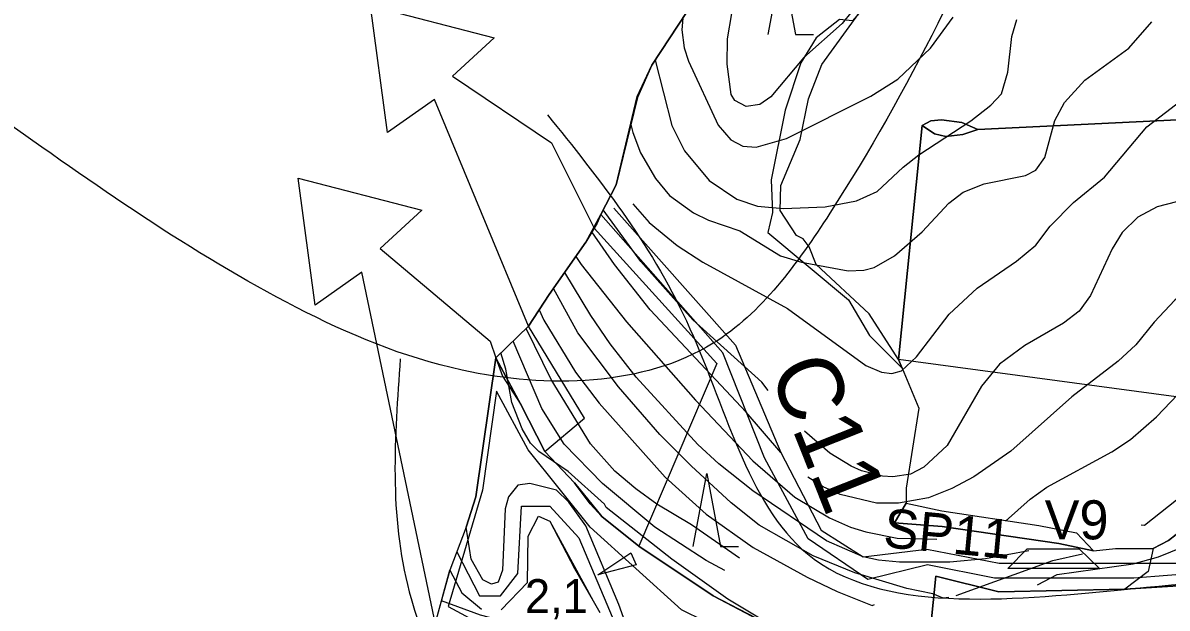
# Model space of a CAD drawing. Extents: x -684583 to -680383, y -1157874 to -1154904.
# Drawn here: x -683807 to -683367.4, y -1156883.6 to -1156658.6 of the extents above; entities that cross this region are included whole.
import ezdxf

# ---------------------------------------------------------------- set-up
doc = ezdxf.new("R2010")
doc.units = 0
for name, color, linetype in [('01_OBVOD PÚ', 7, 'Continuous'), ('01_PRVKY PRŮZKUMU', 7, 'Continuous'), ('01_SPRÁV_HRANICE', 7, 'Continuous'), ('01_VRSTEVNICE', 7, 'Continuous'), ('02_KULTURY STAV', 7, 'Continuous'), ('03_PC_OBJEKTY_NÁVRH', 7, 'Continuous'), ('03_PC_POPIS_STAV', 7, 'Continuous'), ('03_PC_STAV', 7, 'Continuous'), ('05_VHO_V_TOK', 7, 'Continuous'), ('06_BIOGEOGRAFIE', 7, 'Continuous'), ('06_ÚSES_BK', 7, 'Continuous')]:
    doc.layers.add(name, color=color, linetype=linetype)

msp = doc.modelspace()

# ---------------------------------------------------------------- linework, layer by layer
at = {"layer": '01_OBVOD PÚ'}
for points in [[(-683524.73, -1156612.92), (-683565.38, -1156674.86), (-683570.93, -1156687.37), (-683579.12, -1156720.91), (-683585.06, -1156732.32), (-683586.41, -1156735.62), (-683590.79, -1156742.99), (-683604.88, -1156763.1), (-683612.82, -1156775.26), (-683625.32, -1156787.43), (-683633.07, -1156840.81), (-683636.72, -1156852.51)], [(-683636.72, -1156852.51), (-683643.02, -1156869.04), (-683649.36, -1156892.03), (-683671.07, -1156923.59), (-683731.15, -1157006.91), (-683731.15, -1157006.91), (-683753.8, -1157039.59), (-683758.87, -1157046.08), (-683790.05, -1157085.64), (-683814.83, -1157112.74)], [(-683355.2, -1156936.88), (-683380.8, -1156922.96), (-683394.92, -1156921.16), (-683404.54, -1156921.9), (-683418.18, -1156922.4), (-683413.73, -1156906.92), (-683459.39, -1156901.7), (-683456.29, -1156871.3), (-683432.04, -1156877.37), (-683383.68, -1156876.28), (-683357.1, -1156874.68)], [(-683357.1, -1156874.68), (-683383.68, -1156876.28), (-683432.04, -1156877.37), (-683456.29, -1156871.3), (-683459.39, -1156901.7), (-683413.22, -1156907.01), (-683418.18, -1156922.4), (-683394.92, -1156921.16), (-683380.8, -1156922.96), (-683355.2, -1156936.88)]]:
    msp.add_lwpolyline(points, dxfattribs=at)
at = {"layer": '01_PRVKY PRŮZKUMU'}
msp.add_lwpolyline([(-683356.94, -1156938.03), (-683380.59, -1156925.22), (-683395.1, -1156922.91), (-683418.63, -1156924.37), (-683420.21, -1156922.66), (-683416.44, -1156909.37), (-683459.35, -1156905.59), (-683501.04, -1156910.34), (-683553.95, -1156884.24), (-683589.06, -1156852.53), (-683612.95, -1156822.77), (-683625.02, -1156800.2), (-683630.51, -1156838.26), (-683643.68, -1156883.02), (-683591.38, -1156911.2), (-683539.08, -1156946.2), (-683515.55, -1156959.38), (-683497.63, -1156981.82), (-683487.39, -1157002.43), (-683470.08, -1157010.97), (-683441.67, -1157010.97), (-683424.51, -1157001.8), (-683389.86, -1156998.77), (-683362.19, -1157001.09)], dxfattribs=at)
at = {"layer": '01_SPRÁV_HRANICE'}
for points in [[(-683524.73, -1156612.92), (-683565.38, -1156674.86), (-683570.93, -1156687.37), (-683579.12, -1156720.91), (-683585.06, -1156732.32), (-683586.41, -1156735.62), (-683590.79, -1156742.99), (-683604.88, -1156763.1), (-683612.82, -1156775.26), (-683625.32, -1156787.43), (-683633.07, -1156840.81), (-683636.72, -1156852.51)], [(-683636.72, -1156852.51), (-683643.02, -1156869.04), (-683649.36, -1156892.03), (-683671.07, -1156923.59), (-683731.15, -1157006.91), (-683731.15, -1157006.91), (-683753.8, -1157039.59), (-683758.87, -1157046.08), (-683790.05, -1157085.64), (-683814.83, -1157112.74)]]:
    msp.add_lwpolyline(points, dxfattribs=at)
at = {"layer": '01_VRSTEVNICE'}
for points in [[(-683572.71, -1156728.24), (-683566.43, -1156735.37), (-683555.73, -1156744.22), (-683545.75, -1156750.63), (-683513.23, -1156768.46), (-683483.13, -1156790.29), (-683477.14, -1156792.86), (-683473.14, -1156793.43), (-683469.43, -1156792.43), (-683463.73, -1156787.01), (-683451.18, -1156770.6), (-683440.48, -1156760.62), (-683425.36, -1156750.21), (-683417.94, -1156744.07), (-683412.38, -1156736.8), (-683403.39, -1156727.67), (-683391.55, -1156717.97), (-683375.29, -1156698.57), (-683353.75, -1156682.02), (-683350.9, -1156679.03), (-683344.48, -1156669.18), (-683338.35, -1156661.34), (-683330.07, -1156653.92)], [(-683488.55, -1156654.21), (-683492.26, -1156658.91), (-683506.95, -1156671.89), (-683519.65, -1156687.01), (-683523.92, -1156690.01), (-683529.2, -1156690.72), (-683533.48, -1156688.44), (-683534.91, -1156686.16), (-683536.48, -1156674.46), (-683536.33, -1156664.76), (-683534.62, -1156655.06)], [(-683573.46, -1156697.72), (-683572.71, -1156700.71), (-683569.71, -1156708.55), (-683564.01, -1156718.4), (-683558.59, -1156724.96), (-683549.46, -1156731.66), (-683543.61, -1156734.52), (-683531.63, -1156738.51), (-683515.94, -1156748.21), (-683507.95, -1156750.63), (-683489.98, -1156753.91), (-683483.98, -1156753.63), (-683479.99, -1156752.63), (-683472.15, -1156748.21), (-683461.59, -1156738.94), (-683451.32, -1156727.95), (-683445.76, -1156723.67), (-683437.77, -1156720.54), (-683421.79, -1156717.26), (-683417.94, -1156715.26), (-683414.37, -1156710.41), (-683410.52, -1156696.14), (-683406.82, -1156689.3), (-683399.11, -1156680.6), (-683382.14, -1156668.33), (-683373.29, -1156658.2)], [(-683564.15, -1156672.99), (-683557.73, -1156698.14), (-683552.88, -1156707.84), (-683543.33, -1156719.25), (-683532.77, -1156726.38), (-683524.78, -1156729.09), (-683514.8, -1156729.95), (-683498.82, -1156729.38), (-683486.84, -1156727.1), (-683478.85, -1156723.39), (-683468.86, -1156714.12), (-683462.87, -1156709.41), (-683442.9, -1156696.29), (-683435.2, -1156690.3), (-683431.06, -1156685.87), (-683428.64, -1156677.6), (-683427.07, -1156663.91), (-683425.21, -1156657.35)], [(-683553.5, -1156656.76), (-683553.88, -1156661.34), (-683553.03, -1156668.19), (-683551.31, -1156673.32), (-683539.9, -1156698), (-683535.05, -1156703.56), (-683530.49, -1156705.99), (-683525.35, -1156706.41), (-683513.66, -1156703.13), (-683481.28, -1156686.87), (-683470.86, -1156680.31), (-683458.31, -1156668.33), (-683449.61, -1156656.49)], [(-683251.9, -1156698), (-683255.04, -1156700.57), (-683268.88, -1156708.98), (-683291.13, -1156719.82), (-683314.24, -1156736.8), (-683322.8, -1156741.51), (-683338.77, -1156748.64), (-683355.04, -1156757.48), (-683364.45, -1156765.18), (-683372.44, -1156773.74), (-683379.43, -1156782.44), (-683386.27, -1156788.72), (-683404.1, -1156802.41), (-683427.5, -1156823.24), (-683441.76, -1156833.08), (-683450.18, -1156837.65), (-683459.17, -1156841.21), (-683470.58, -1156843.21), (-683479.13, -1156843.21), (-683493.11, -1156839.93), (-683499.58, -1156836.93), (-683505.52, -1156833.22)], [(-683355.89, -1156725.39), (-683371.3, -1156729.38), (-683378.71, -1156733.38), (-683384.7, -1156739.22), (-683388.56, -1156745.5), (-683396.83, -1156763.47), (-683401.25, -1156769.46), (-683407.24, -1156774.03), (-683422.08, -1156782.59), (-683431.78, -1156789.86), (-683438.77, -1156798.28), (-683451.89, -1156821.1), (-683460.88, -1156829.37), (-683466.01, -1156832.08), (-683472.86, -1156833.08), (-683476.85, -1156832.94), (-683484.84, -1156830.8), (-683488.83, -1156829.09), (-683496.96, -1156824.1), (-683506.81, -1156815.54)], [(-683520.7, -1156800), (-683523.17, -1156796.7), (-683549.6, -1156772.74), (-683569.57, -1156750.35), (-683584.1, -1156730.47)], [(-683515.79, -1156823.81), (-683529.2, -1156808.26), (-683566, -1156768.89), (-683579.7, -1156751.49), (-683588.42, -1156739)], [(-683594.62, -1156748.46), (-683592.54, -1156751.49), (-683575.13, -1156773.6), (-683548.6, -1156803.7), (-683526.63, -1156826.95), (-683510.52, -1156840.93), (-683497.11, -1156848.92), (-683489.12, -1156852.48), (-683483.13, -1156854.34), (-683471.15, -1156856.76), (-683455.88, -1156857.05)], [(-683420.51, -1156861.61), (-683437.2, -1156864.61), (-683450.89, -1156865.89), (-683470.29, -1156865.89), (-683478.28, -1156865.18), (-683484.27, -1156863.89), (-683498.25, -1156857.76), (-683526.63, -1156838.5), (-683539.62, -1156828.09), (-683547.75, -1156820.67), (-683571.43, -1156794.85), (-683581.41, -1156782.02), (-683588.83, -1156771.18), (-683598.89, -1156754.55)], [(-683451.32, -1156879.58), (-683453.46, -1156879.73), (-683457.45, -1156878.16), (-683467.44, -1156876.02), (-683487.41, -1156870.03), (-683503.38, -1156863.47), (-683524.21, -1156851.77), (-683534.91, -1156843.07), (-683550.31, -1156828.95), (-683562.3, -1156816.82), (-683578.27, -1156798.56), (-683593.82, -1156777.74), (-683603.22, -1156760.73)], [(-683429.5, -1156850.2), (-683420.08, -1156841.78), (-683413.66, -1156837.08), (-683388.7, -1156823.53), (-683381.57, -1156818.82), (-683371.58, -1156810.12), (-683349.61, -1156787.15), (-683341.06, -1156781.3), (-683335.92, -1156779.31), (-683325.65, -1156777.59), (-683305.11, -1156777.17), (-683297.41, -1156776.31), (-683284.57, -1156772.6), (-683272.16, -1156766.04)], [(-683608.73, -1156768.99), (-683606.94, -1156772.89), (-683594.68, -1156792.86), (-683585.69, -1156804.84), (-683560.3, -1156833.22), (-683544.47, -1156847.49), (-683526.49, -1156860.33), (-683505.67, -1156871.74), (-683494.25, -1156877.16), (-683480.7, -1156882.58), (-683479.85, -1156882.15)], [(-683531.77, -1156864.46), (-683550.17, -1156851.63), (-683563.44, -1156843.64), (-683571.57, -1156837.79), (-683579.56, -1156830.94), (-683588.97, -1156820.39), (-683604.09, -1156795.71), (-683613.74, -1156776.16)], [(-683537.33, -1156869.17), (-683544.47, -1156865.32), (-683564.29, -1156852.48), (-683584.41, -1156835.65), (-683599.1, -1156820.53), (-683607.66, -1156806.84), (-683618.68, -1156780.96)], [(-683355.46, -1156920.38), (-683357.32, -1156920.38), (-683359.6, -1156918.67), (-683379, -1156909.97), (-683394.41, -1156905.12), (-683416.09, -1156903.12), (-683451.6, -1156904.12), (-683467.44, -1156903.26), (-683488.83, -1156898.7), (-683514.51, -1156891.42), (-683524.64, -1156887.14), (-683536.19, -1156880.15), (-683557.73, -1156864.75), (-683582.98, -1156844.92), (-683583.55, -1156843.64), (-683597.53, -1156831.09), (-683608.8, -1156823.38), (-683612.08, -1156820.24), (-683615.22, -1156814.68), (-683619.21, -1156804.55), (-683621.49, -1156791.72), (-683623.36, -1156785.52)], [(-683377.43, -1156851.63), (-683376.15, -1156851.77), (-683360.74, -1156839.5), (-683354.04, -1156831.51), (-683343.2, -1156815.97), (-683336.49, -1156810.12), (-683328.5, -1156806.69), (-683318.95, -1156805.7)], [(-683417.2, -1156874.64), (-683409.69, -1156870.63), (-683380.43, -1156866.6), (-683370.73, -1156863.89), (-683361.31, -1156860.04), (-683353.04, -1156854.91), (-683343.05, -1156844.35), (-683334.49, -1156831.66), (-683329.5, -1156826.95), (-683322.66, -1156824.67), (-683321.23, -1156825.24), (-683321.23, -1156827.8), (-683323.8, -1156833.94), (-683324.79, -1156843.07), (-683326.65, -1156852.2), (-683334.21, -1156875.02), (-683341.63, -1156888.71), (-683343.48, -1156893.28), (-683343.91, -1156904.12), (-683340.48, -1156911.54), (-683337.2, -1156916.1), (-683322.65, -1156927.66)], [(-683448.47, -1156878.73), (-683411.38, -1156865.32), (-683399.97, -1156862.75)], [(-683361.6, -1157020.95), (-683377.57, -1157017.24), (-683390.7, -1157015.95), (-683403.25, -1157017.38), (-683419.51, -1157020.8), (-683438.34, -1157026.79), (-683453.74, -1157029.36), (-683464.3, -1157028.65), (-683471.43, -1157026.65), (-683476.71, -1157024.37), (-683484.27, -1157019.8), (-683492.26, -1157012.96), (-683503.81, -1156998.55), (-683513.08, -1156984.28), (-683523.5, -1156971.16), (-683530.2, -1156964.89), (-683542.04, -1156955.33), (-683549.74, -1156947.77), (-683573.14, -1156918.67), (-683594.96, -1156898.13), (-683604.95, -1156893.14), (-683631.19, -1156886.29), (-683646.27, -1156880.82)]]:
    msp.add_lwpolyline(points, dxfattribs=at)
at = {"layer": '02_KULTURY STAV'}
for points in [[(-683432.04, -1156877.37), (-683456.29, -1156871.3), (-683458.99, -1156897.79), (-683470.08, -1156900.87), (-683483.78, -1156902.23), (-683501.85, -1156899.69), (-683541.87, -1156878.91), (-683570.35, -1156859.85), (-683584.63, -1156848.32), (-683595.13, -1156835.42), (-683606.54, -1156823.38), (-683615.78, -1156805.32), (-683625.32, -1156787.43), (-683612.82, -1156775.26), (-683604.88, -1156763.1), (-683590.79, -1156742.99), (-683585.06, -1156732.32), (-683579.12, -1156720.91), (-683571, -1156686.89), (-683565.38, -1156674.86), (-683524.73, -1156612.92)], [(-683520.74, -1156663.07), (-683515.49, -1156635.07), (-683510.24, -1156663.07), (-683503.24, -1156663.07)], [(-683250.43, -1156639.58), (-683251.92, -1156662.61), (-683255.02, -1156690.63), (-683440.19, -1156699.57), (-683446.37, -1156696.93), (-683454.14, -1156695.86), (-683458.28, -1156696.29), (-683461.57, -1156698.06), (-683470.65, -1156788), (-683481.96, -1156770.49), (-683502.22, -1156751.48), (-683504.93, -1156744.71), (-683507.26, -1156741.71), (-683509.77, -1156740.38), (-683516.1, -1156730.82), (-683515.85, -1156721.2), (-683508.45, -1156703.51), (-683505.19, -1156687.78), (-683500.09, -1156674.67), (-683485.88, -1156655.07)], [(-683493.37, -1156657.35), (-683502.3, -1156664.33), (-683508.16, -1156673.98), (-683514.12, -1156692.19), (-683519.56, -1156719.01), (-683519.03, -1156731.5), (-683520.89, -1156739.21), (-683489.86, -1156765.12), (-683481.81, -1156778.8), (-683469.26, -1156791.35), (-683462.87, -1156806.79), (-683467.74, -1156837.5), (-683467.68, -1156843.29), (-683472.14, -1156850.86), (-683453.92, -1156852.18), (-683409.09, -1156858.82), (-683395.73, -1156861.57), (-683387.31, -1156860.69), (-683372.79, -1156860.68), (-683374.76, -1156869.57), (-683383.68, -1156876.28), (-683432.04, -1156877.37)], [(-683575.07, -1156890.75), (-683578.07, -1156882.16), (-683590.81, -1156851.97), (-683597.23, -1156842.93), (-683602, -1156838.28), (-683612.25, -1156835.71), (-683616.87, -1156836.4), (-683620.5, -1156840.84), (-683621.81, -1156845.41), (-683622.8, -1156868.99), (-683624.44, -1156873.64), (-683627.05, -1156874.36), (-683630.39, -1156872.73), (-683634.76, -1156864.74), (-683636.72, -1156852.51), (-683633.07, -1156840.81), (-683625.32, -1156787.43), (-683615.78, -1156805.32), (-683606.54, -1156823.38), (-683595.13, -1156835.42), (-683584.63, -1156848.32), (-683570.35, -1156859.85), (-683541.87, -1156878.91), (-683515.11, -1156893)], [(-683549.57, -1156859.91), (-683544.32, -1156831.91), (-683539.07, -1156859.91), (-683532.07, -1156859.91)], [(-683575.07, -1156890.75), (-683578.07, -1156882.16), (-683590.81, -1156851.97), (-683597.23, -1156842.93), (-683602, -1156838.28), (-683612.25, -1156835.71), (-683616.87, -1156836.4), (-683620.5, -1156840.84), (-683621.81, -1156845.41), (-683622.8, -1156868.99), (-683624.44, -1156873.64), (-683627.05, -1156874.36), (-683630.39, -1156872.73), (-683634.76, -1156864.74), (-683636.72, -1156852.51), (-683643.02, -1156869.04), (-683638.42, -1156877.73), (-683630.81, -1156883.98)], [(-683623.28, -1156884.31), (-683613.15, -1156873.71), (-683612.91, -1156855.89), (-683609, -1156848.24), (-683604.61, -1156850.24), (-683595.11, -1156868.31), (-683587.96, -1156880.75), (-683585.36, -1156885.34)], [(-683623.28, -1156884.31), (-683613.15, -1156873.71), (-683612.91, -1156855.89), (-683609, -1156848.24), (-683604.61, -1156850.24), (-683587.96, -1156880.75), (-683585.36, -1156885.34)], [(-683648.19, -1156887.79), (-683643.02, -1156869.04), (-683638.42, -1156877.73), (-683630.81, -1156883.98)], [(-683357.1, -1156874.68), (-683383.68, -1156876.28), (-683432.04, -1156877.37), (-683456.29, -1156871.3), (-683459.39, -1156901.7), (-683413.22, -1156907.01), (-683380.86, -1156914.04), (-683355.11, -1156929.55)]]:
    msp.add_lwpolyline(points, dxfattribs=at)
for points in [[(-683485.88, -1156655.07), (-683488.33, -1156657.8), (-683493.37, -1156657.35), (-683502.3, -1156664.33), (-683508.16, -1156673.98), (-683514.12, -1156692.19), (-683519.56, -1156719.01), (-683519.03, -1156731.5), (-683520.89, -1156739.21), (-683489.86, -1156765.12), (-683481.81, -1156778.8), (-683469.26, -1156791.35), (-683470.65, -1156788), (-683481.96, -1156770.49), (-683502.22, -1156751.48), (-683504.93, -1156744.71), (-683507.26, -1156741.71), (-683509.77, -1156740.38), (-683516.1, -1156730.82), (-683515.85, -1156721.2), (-683508.45, -1156703.51), (-683505.19, -1156687.78), (-683500.09, -1156674.67)], [(-683461.57, -1156698.06), (-683456.76, -1156701.28), (-683452.45, -1156702.26), (-683445.89, -1156701.53), (-683440.19, -1156699.57), (-683255.02, -1156690.63), (-683256.28, -1156728.52), (-683263.19, -1156747.9), (-683277, -1156775.83), (-683293.02, -1156802.11), (-683296.59, -1156809.49), (-683303.1, -1156808.51), (-683311.62, -1156809.46), (-683470.65, -1156788)], [(-683461.57, -1156698.06), (-683458.28, -1156696.29), (-683454.14, -1156695.86), (-683446.37, -1156696.93), (-683440.19, -1156699.57), (-683445.89, -1156701.53), (-683452.45, -1156702.26), (-683456.76, -1156701.28)], [(-683470.65, -1156788), (-683469.26, -1156791.35), (-683462.87, -1156806.79), (-683467.74, -1156837.5), (-683467.68, -1156843.29), (-683453.95, -1156846.2), (-683416.75, -1156851.8), (-683402.2, -1156854.64), (-683395.73, -1156861.57), (-683387.31, -1156860.69), (-683372.79, -1156860.68), (-683366.97, -1156857.64), (-683358.08, -1156850.72), (-683354.26, -1156850.68), (-683348.7, -1156844.45), (-683343.91, -1156825.46), (-683324.44, -1156813.27), (-683311.62, -1156809.46)], [(-683303.58, -1156846.39), (-683306.11, -1156845.61), (-683317.39, -1156851.59), (-683327.99, -1156859.69), (-683336.87, -1156864.5), (-683341.9, -1156865.49), (-683346.55, -1156863.74), (-683352.01, -1156858.95), (-683337.5, -1156844.95), (-683329.43, -1156828.36), (-683343.91, -1156825.46), (-683348.7, -1156844.45), (-683354.26, -1156850.68), (-683358.08, -1156850.72), (-683366.97, -1156857.64), (-683372.79, -1156860.68), (-683374.76, -1156869.57), (-683383.68, -1156876.28), (-683357.1, -1156874.68), (-683352.99, -1156875.58), (-683340.48, -1156874.45), (-683323.26, -1156864.81), (-683311.13, -1156860.63), (-683306.38, -1156857.92)], [(-683467.68, -1156843.29), (-683453.95, -1156846.2), (-683416.75, -1156851.8), (-683402.2, -1156854.64), (-683395.73, -1156861.57), (-683409.09, -1156858.82), (-683453.92, -1156852.18), (-683472.14, -1156850.86)]]:
    msp.add_lwpolyline(points, close=True, dxfattribs=at)
at = {"layer": '03_PC_OBJEKTY_NÁVRH'}
msp.add_lwpolyline([(-683579.97, -1156729.89), (-683533.3, -1156782.53), (-683515.79, -1156823.81), (-683500.35, -1156853.59), (-683484.27, -1156863.89), (-683459.82, -1156860.96), (-683431.98, -1156866.28), (-683360.96, -1156866.28)], dxfattribs=at)
msp.add_lwpolyline([(-683428.68, -1156868.33), (-683421.18, -1156860.83), (-683401.18, -1156860.83), (-683393.42, -1156868.33)], close=True, dxfattribs=at)
at = {"layer": '03_PC_STAV'}
msp.add_lwpolyline([(-683292.75, -1156847.09), (-683341.45, -1156869.01), (-683380.18, -1156872.12), (-683433.77, -1156872.12), (-683459.52, -1156866.97), (-683482.47, -1156872.62), (-683505.37, -1156856.94), (-683522.11, -1156825.77), (-683538.17, -1156785.41), (-683585.06, -1156732.32)], dxfattribs=at)
at = {"layer": '05_VHO_V_TOK'}
msp.add_lwpolyline([(-683640.3, -1156862.01), (-683631.63, -1156878.88), (-683623.57, -1156878.88), (-683616.93, -1156870.35), (-683615.42, -1156844.35), (-683604.61, -1156844.35), (-683593.47, -1156856.6), (-683579.25, -1156890.27), (-683576.17, -1156906.63), (-683556.43, -1156916.81), (-683533.66, -1156919.62), (-683513.12, -1156934.95), (-683503.17, -1156938.75), (-683482.31, -1156934.13), (-683475.08, -1156937.45), (-683473.66, -1156947.17), (-683484.44, -1156960.81), (-683493.81, -1156982.15), (-683492.15, -1156992.1), (-683470.34, -1157006.92), (-683446.29, -1157008.7), (-683426.97, -1156997.79), (-683378.73, -1156994.28), (-683361.67, -1156998.74)], dxfattribs=at)
msp.add_lwpolyline([(-683573.47, -1156862.38), (-683571.44, -1156866.95), (-683586.16, -1156870.76)], close=True, dxfattribs=at)
at = {"layer": '06_BIOGEOGRAFIE'}
for points in [[(-682624.87, -1154935.44), (-682669.05, -1155140.04), (-682739.65, -1155253.72), (-682834.36, -1155382.91), (-682941.12, -1155661.96), (-683008.28, -1155760.14), (-683056.49, -1155810.09), (-683084.04, -1155808.37), (-683154.45, -1155886.49), (-683231.94, -1156062.19), (-683280.08, -1156211.64), (-683362.74, -1156430.39), (-683497.05, -1156731.83), (-683541.82, -1156781.78), (-683638.25, -1156792.12), (-683701.96, -1156768), (-683817.33, -1156693.94)], [(-683605.53, -1156693.94), (-683552.15, -1156773.17), (-683505.66, -1156862.74), (-683385.12, -1156876.52), (-683240.48, -1156867.91), (-682983.91, -1156935.09), (-682923.69, -1156998.38), (-682921.97, -1157094.84), (-682923.69, -1157198.19), (-682892.7, -1157272.26), (-682746.33, -1157329.1), (-682572.41, -1157337.72), (-682417.44, -1157289.49), (-682386.73, -1157266.62)], [(-683662.04, -1156787.77), (-683658.6, -1156877.34), (-683631.05, -1156927.29), (-683541.5, -1156975.52), (-683489.85, -1157028.92), (-683414.08, -1157027.2), (-683362.42, -1157025.48), (-683360.7, -1157063.37), (-683464.02, -1157132.27), (-683493.29, -1157163.28), (-683474.35, -1157189.11), (-683407.19, -1157171.89), (-683317.65, -1157115.05), (-683269.44, -1157104.71), (-683207.44, -1157173.61), (-683186.78, -1157259.74), (-683105.85, -1157416.48), (-683069.69, -1157530.17), (-683073.13, -1157580.12), (-683097.24, -1157628.35), (-683264.27, -1157657.63), (-683431.3, -1157647.3), (-683531.17, -1157605.96), (-683636.21, -1157542.23), (-683651.71, -1157521.56), (-683682.7, -1157519.83), (-683708.53, -1157528.45), (-683818.74, -1157547.39), (-683870.4, -1157518.11), (-683980.6, -1157521.56), (-684052.92, -1157490.55), (-684171.74, -1157400.98), (-684213.07, -1157375.14), (-684250.95, -1157388.92), (-684249.23, -1157437.15), (-684237.17, -1157466.44), (-684170.02, -1157518.11), (-684097.7, -1157562.9), (-684011.6, -1157605.96), (-683953.05, -1157602.51), (-683891.06, -1157626.63), (-683835.96, -1157619.74), (-683789.47, -1157599.07), (-683713.7, -1157578.4), (-683625.88, -1157592.18), (-683551.84, -1157667.97), (-683445.07, -1157736.87), (-683346.92, -1157771.32), (-683179.89, -1157767.87), (-683081.74, -1157773.04), (-683016.71, -1157810.65), (-682999.16, -1157844)]]:
    msp.add_spline(points, degree=3, dxfattribs=at)
at = {"layer": '06_ÚSES_BK'}
for points in [[(-683603.98, -1156704.72), (-683587.53, -1156737.5), (-683540.45, -1156789.59), (-683570.35, -1156859.85), (-683584.63, -1156848.32), (-683589.07, -1156843.46), (-683595.13, -1156835.42), (-683606.54, -1156823.38), (-683591.29, -1156810.56), (-683612.82, -1156775.26), (-683648.92, -1156688.09), (-683666.93, -1156700.78), (-683673.48, -1156652.05), (-683625.99, -1156664.34), (-683641.96, -1156679.08), (-683603.98, -1156704.72)], [(-683701.32, -1156718.39), (-683653.83, -1156730.68), (-683669.8, -1156745.42), (-683627.49, -1156781.02), (-683625.32, -1156787.43), (-683622.78, -1156794.5), (-683615.78, -1156805.32), (-683606.54, -1156823.38), (-683595.13, -1156835.42), (-683584.63, -1156848.32), (-683570.35, -1156859.85), (-683541.87, -1156878.91), (-683515.11, -1156893), (-683501.85, -1156899.69), (-683483.78, -1156902.23), (-683470.08, -1156900.87), (-683458.99, -1156897.79), (-683459.39, -1156901.7), (-683413.73, -1156906.92), (-683418.18, -1156922.4), (-683394.92, -1156921.16), (-683380.8, -1156922.96), (-683355.2, -1156936.88)], [(-683648.97, -1156887.36), (-683676.76, -1156754.43), (-683694.77, -1156767.12), (-683701.32, -1156718.39)]]:
    msp.add_lwpolyline(points, dxfattribs=at)

# ---------------------------------------------------------------- texts
at = {"layer": '03_PC_OBJEKTY_NÁVRH'}
msp.add_text('V9', height=15, dxfattribs=at).set_placement((-683414.49, -1156857.16))
msp.add_text('SP11', height=15, rotation=354.5577, dxfattribs=at).set_placement((-683476.83, -1156860.1))
at = {"layer": '03_PC_POPIS_STAV'}
msp.add_text('C11', height=25, rotation=291.6985, dxfattribs=at).set_placement((-683520.59, -1156792.02))
at = {"layer": '05_VHO_V_TOK'}
msp.add_text('2,1', height=13, dxfattribs=at).set_placement((-683614.16, -1156885.46))

doc.saveas('drawing.dxf')
